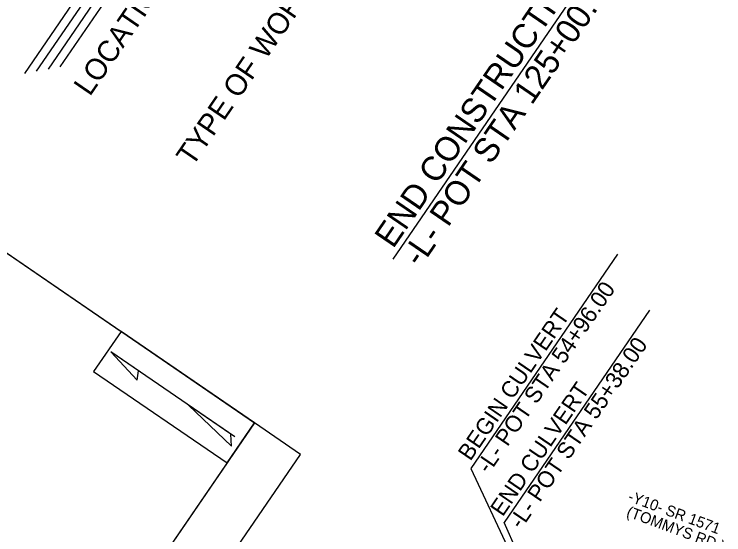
# Model space of a CAD drawing. Extents: x 2312641 to 2338852, y 590461 to 618614.
# Drawn here: x 2320204 to 2326043, y 602179 to 606464 of the extents above; entities that cross this region are included whole.
import ezdxf

# ---------------------------------------------------------------- set-up
doc = ezdxf.new("R2010")
doc.units = 0
for name, color, linetype in [('Default', 7, 'Continuous'), ('Exist Property Iron Pin CELL', 7, 'Continuous'), ('Exist Property Iron Pin Cogo Number', 7, 'Continuous'), ('Exist Property Monument Cogo Number', 7, 'Continuous'), ('Exist Structure Minor Pipes RCP 15 Inch Text', 7, 'Continuous')]:
    doc.layers.add(name, color=color, linetype=linetype)

msp = doc.modelspace()

# ---------------------------------------------------------------- linework, layer by layer
at = {"layer": 'Exist Property Iron Pin CELL'}
msp.add_line((2322019.8, 602984.5), (2320999.1, 603684.1), dxfattribs=at)
for points in [[(2320999.1, 603684.1), (2321216.8, 603452.1), (2321226.9, 603528)], [(2321638.4, 603245.9), (2321992.3, 602909.4), (2321985.8, 603007.9)]]:
    msp.add_lwpolyline(points, close=True, dxfattribs=at)
at = {"layer": 'Exist Property Iron Pin Cogo Number'}
for p, q in [((2320290.3, 605975.5), (2323662, 610895)), ((2320387.7, 605993.7), (2323680.2, 610797.7)), ((2320485.1, 606011.8), (2323698.2, 610700.5)), ((2320582.3, 606030), (2323716.5, 610603.1))]:
    msp.add_line(p, q, dxfattribs=at)
for points in [[(2315736.3, 601363.6), (2318606, 605551.1), (2322182.1, 603100.3), (2319312.3, 598912.9)], [(2321956.1, 602770.5), (2322182.1, 603100.3), (2321083.4, 603853.3), (2320857.4, 603523.5)], [(2322182.1, 603100.3), (2319312.3, 598912.9), (2319691, 598653.4), (2322560.7, 602840.8)]]:
    msp.add_lwpolyline(points, close=True, dxfattribs=at)
at = {"layer": 'Exist Property Monument Cogo Number'}
msp.add_lwpolyline([(2321956.1, 602770.5), (2319312.3, 598912.9), (2315736.3, 601363.6), (2318606, 605551.1), (2321083.4, 603853.3), (2320857.4, 603523.5)], dxfattribs=at)
at = {"layer": 'Exist Structure Minor Pipes RCP 15 Inch Text'}
for p, q in [((2325213.2, 607213.6), (2323318.4, 604448.6)), ((2325169, 604487.7), (2323961.5, 602725.8)), ((2325432.5, 604028), (2324234.7, 602280.3)), ((2323961.5, 602725.8), (2324923.1, 600661.6)), ((2324955.6, 600688.1), (2324234.7, 602280.3))]:
    msp.add_line(p, q, dxfattribs=at)

# ---------------------------------------------------------------- texts
at = {"layer": 'Default'}
for s, p in [('-L- POT STA 54+96.00', (2324109.3, 602675.6)), ('BEGIN CULVERT', (2323957.2, 602779.8))]:
    msp.add_text(s, height=135, rotation=55.57611, dxfattribs=at).set_placement(p)
at = {"layer": 'Exist Property Iron Pin Cogo Number'}
for s, height, p in [('LOCATION: ', 175, (2320826.6, 605781.1)), ('TYPE OF WORK:', 175.001, (2321670.6, 605202.9))]:
    msp.add_text(s, height=height, rotation=55.57608, dxfattribs=at).set_placement(p)
at = {"layer": 'Exist Structure Minor Pipes RCP 15 Inch Text'}
for s, height, rotation, p in [('END CONSTRUCTION', 200, 55.57611, (2323321.6, 604527.7)), ('-L- POT STA 125+00.00', 200, 55.57611, (2323547, 604373.3)), ('-L- POT STA 55+38.00', 135, 55.57611, (2324375.1, 602217.7)), ('END CULVERT', 135, 55.57611, (2324223, 602321.9)), ('-Y10- SR 1571', 90, 339.68138, (2325247.5, 602459.3)), ('(TOMMYS RD.)', 90, 339.68138, (2325235, 602332.9))]:
    msp.add_text(s, height=height, rotation=rotation, dxfattribs=at).set_placement(p)

doc.saveas('drawing.dxf')
